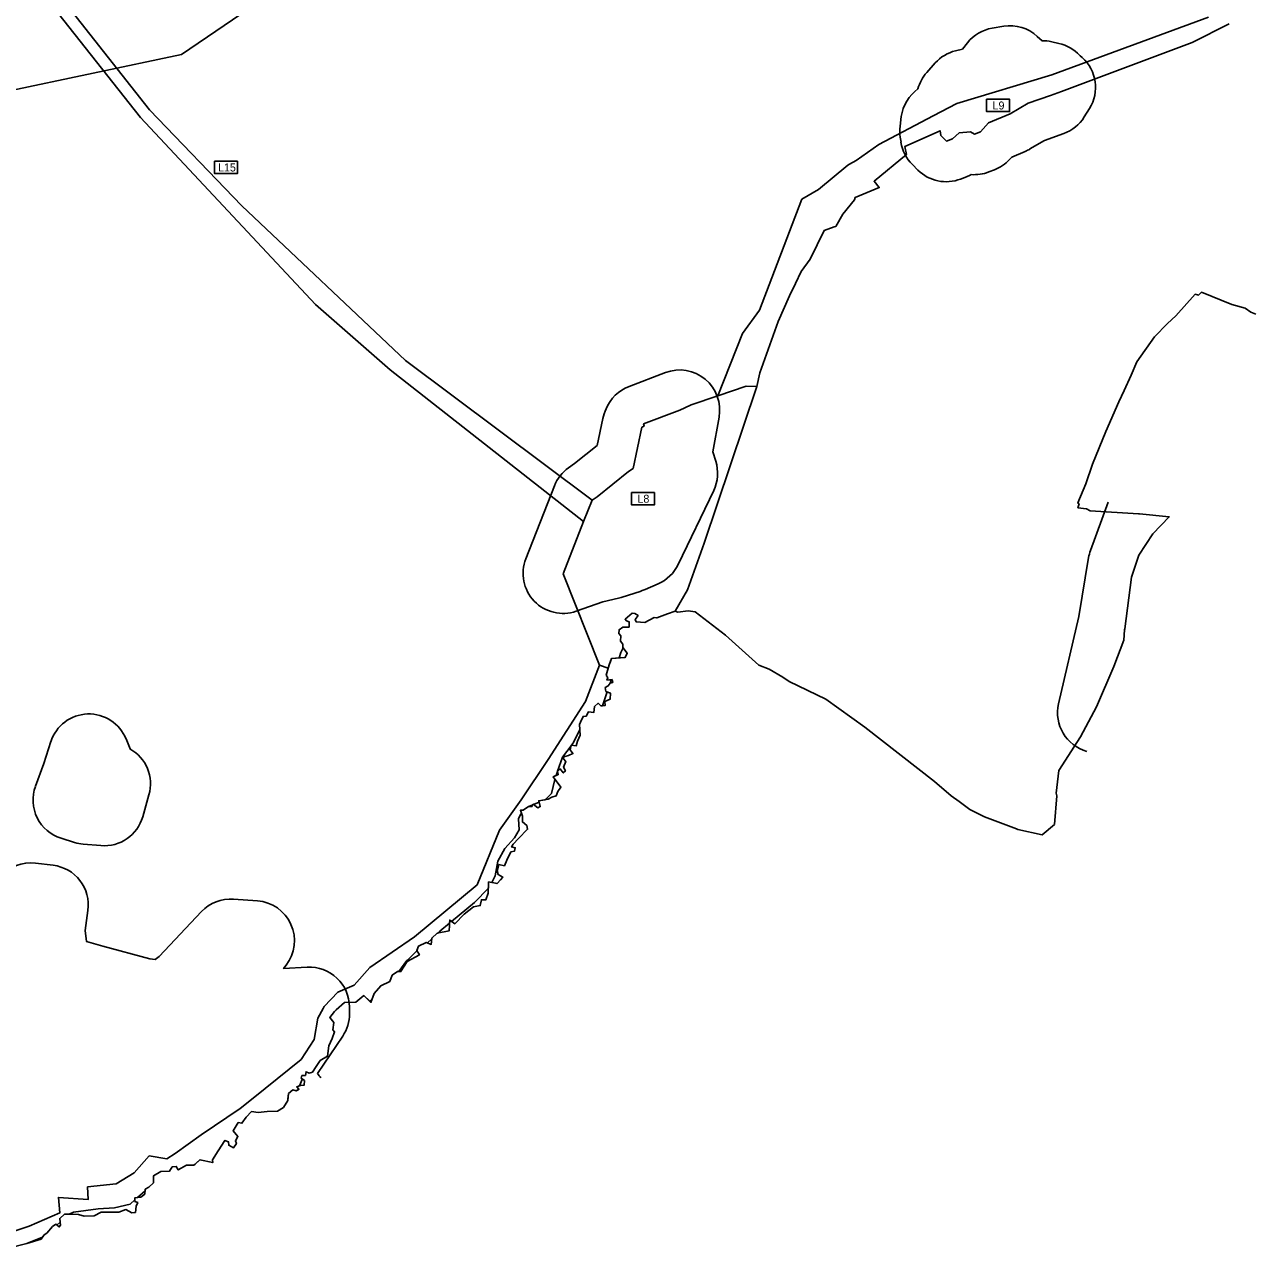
# Model space of a CAD drawing. Extents: x -547623 to -532764, y -1096714 to -1086523.
# Drawn here: x -541756 to -540221, y -1094468 to -1092939 of the extents above; entities that cross this region are included whole.
import ezdxf

# ---------------------------------------------------------------- set-up
doc = ezdxf.new("R2010")
doc.units = 0
for name, color, linetype in [('Vrstva 22', 7, 'Continuous'), ('Vrstva 23', 7, 'Continuous'), ('Vrstva 32', 7, 'Continuous'), ('Vrstva 33', 7, 'Continuous'), ('Vrstva 36', 7, 'Continuous')]:
    doc.layers.add(name, color=color, linetype=linetype)

msp = doc.modelspace()

# ---------------------------------------------------------------- linework, layer by layer
at = {"layer": 'Vrstva 22'}
for points in [[(-541614.2, -1092219.2), (-541528.1, -1092261.5), (-541473.1, -1092334.2), (-541450.6, -1092439.7), (-541395.2, -1092515.1), (-541374.9, -1092586.5), (-541384.1, -1092718), (-541463.6, -1092911.1), (-541559.8, -1092976.5), (-541891.2, -1093046.6)], [(-541777.7, -1094468.4), (-541753.1, -1094462.3), (-541733.3, -1094454.2), (-541731.4, -1094451.4), (-541727.8, -1094449.2), (-541721.1, -1094441), (-541716.9, -1094438.1), (-541715.3, -1094439.3), (-541711.2, -1094435.5), (-541711.8, -1094430.8), (-541705.7, -1094425.4), (-541700.1, -1094425.5), (-541694.7, -1094423.2), (-541663.7, -1094418.8), (-541643.5, -1094417.6), (-541623.8, -1094412.9), (-541617.9, -1094407.7), (-541618, -1094405.2), (-541614.6, -1094404.7), (-541605.1, -1094396.2), (-541604.9, -1094394.3), (-541600.6, -1094391.8), (-541594.8, -1094386.5), (-541594.6, -1094377.6), (-541585.5, -1094372.2), (-541574.6, -1094371.7), (-541571.3, -1094366.4), (-541566.3, -1094365.9), (-541563.8, -1094370.3), (-541553.4, -1094364.4), (-541544.1, -1094364.4), (-541536.7, -1094357.6), (-541520.7, -1094361), (-541520.9, -1094357.7), (-541513.9, -1094346.5), (-541505.5, -1094333.3), (-541500.8, -1094335.3), (-541500.6, -1094339.4), (-541494.5, -1094342.6), (-541491.1, -1094337.3), (-541492.4, -1094334.1), (-541489.1, -1094328.6), (-541495.2, -1094321.4), (-541488.7, -1094311.1), (-541484.1, -1094311.9), (-541479, -1094304.4), (-541472.3, -1094297.4), (-541463.9, -1094298.3), (-541452.7, -1094297.4), (-541439.8, -1094296.8), (-541432.3, -1094292.1), (-541426.7, -1094283.4), (-541425.9, -1094274.8), (-541420.7, -1094270), (-541416.5, -1094271.6), (-541413.9, -1094270), (-541413.5, -1094268.9), (-541415.6, -1094266.6), (-541412.1, -1094265.2), (-541409, -1094257.4), (-541409, -1094257.3), (-541408.5, -1094256.9), (-541410, -1094255.8), (-541409.1, -1094252.4), (-541404.9, -1094252.2), (-541404, -1094247.6), (-541400, -1094249.5), (-541396.1, -1094248), (-541391.4, -1094241.1), (-541386.2, -1094233.4), (-541377.4, -1094228.2), (-541375.6, -1094215), (-541371.4, -1094206), (-541368.4, -1094197.9), (-541370.5, -1094195.2), (-541369.3, -1094186.2), (-541374.2, -1094180), (-541368.6, -1094172.5), (-541356, -1094161.1), (-541341.8, -1094160.7), (-541331.8, -1094152.4), (-541324.5, -1094159.5), (-541321.7, -1094157.7), (-541318.8, -1094150), (-541310.6, -1094140.3), (-541299.5, -1094134.8), (-541296.5, -1094127), (-541289.9, -1094122.4), (-541288, -1094122.5), (-541277.9, -1094108.7), (-541277.4, -1094108.2), (-541276.4, -1094107.2), (-541265.5, -1094096.3), (-541265.7, -1094096), (-541263.3, -1094090.6), (-541253.9, -1094085.9), (-541252.4, -1094086.5), (-541246.9, -1094081.4), (-541246.9, -1094080.6), (-541240.1, -1094074.5), (-541239.5, -1094074.4), (-541237, -1094072), (-541224.7, -1094061.9), (-541224.5, -1094058), (-541222.1, -1094059.7), (-541193.6, -1094036.2), (-541176.2, -1094018.3), (-541175.9, -1094010.3), (-541171.9, -1094011.1), (-541167.8, -1094002.8), (-541164.2, -1093984.5), (-541155.6, -1093968.7), (-541143.4, -1093955.5), (-541137.7, -1093945.2), (-541138.6, -1093931.7), (-541135.7, -1093925.4), (-541134.9, -1093924.7), (-541136.2, -1093920.9), (-541132.7, -1093920.8), (-541126.1, -1093916), (-541125.2, -1093916.2), (-541124.9, -1093915.9), (-541120.6, -1093914.1), (-541120.1, -1093913.4), (-541119.7, -1093913.7), (-541112.8, -1093910.7), (-541113.2, -1093909), (-541105.6, -1093907.7), (-541104.6, -1093907.3), (-541097.1, -1093899.9), (-541093.1, -1093882.3), (-541093, -1093881.9), (-541095.1, -1093879), (-541091.4, -1093877.4), (-541089.7, -1093872.5), (-541089.8, -1093872.3), (-541089.6, -1093872.1), (-541083.6, -1093854.7), (-541072.9, -1093840.3), (-541072.8, -1093839.7), (-541072.5, -1093839.7), (-541069.8, -1093836), (-541061.8, -1093819.8), (-541062.1, -1093813.8), (-541061.2, -1093810.6), (-541057.9, -1093803.5), (-541053.8, -1093803.2), (-541051.2, -1093797.9), (-541044.4, -1093798.8), (-541043.5, -1093791.1), (-541039, -1093787.2), (-541035.6, -1093790.4), (-541033.7, -1093790.3), (-541027.7, -1093773), (-541029.3, -1093772.3), (-541030.1, -1093767.5), (-541026.3, -1093765.5), (-541024, -1093761.9), (-541023.8, -1093761.9), (-541022.4, -1093757.7), (-541028.1, -1093758.2), (-541027, -1093755.2), (-541028.8, -1093752.1), (-541025.3, -1093739.1), (-541022.3, -1093731.1), (-541012.9, -1093730.4), (-541010.5, -1093723.6), (-541007.9, -1093718), (-541008.3, -1093717.5), (-541008.1, -1093713.3), (-541011.2, -1093709.6), (-541010.5, -1093702.9), (-541013.3, -1093700), (-541012.8, -1093695.4), (-541008.3, -1093692.1), (-541000.3, -1093692), (-541000.1, -1093685.6), (-541003.7, -1093684.2), (-541005.3, -1093682.2), (-540996.3, -1093674.6), (-540993.1, -1093674.9), (-540989.1, -1093677.5), (-540992.6, -1093682.7), (-540991.5, -1093685.3), (-540980.8, -1093686.2), (-540969.1, -1093679.8), (-540965.7, -1093680.5), (-540952.4, -1093675.5), (-540942.7, -1093672.1), (-540939.3, -1093673.3), (-540926.5, -1093671.8), (-540917.9, -1093673.1), (-540879.9, -1093702.1), (-540838.1, -1093739.4), (-540825.3, -1093744.7), (-540808.3, -1093754.5), (-540800.3, -1093759.8), (-540754.6, -1093782.1), (-540705.7, -1093817.2), (-540618.6, -1093884.8), (-540597.9, -1093902.7), (-540587.9, -1093910), (-540574.7, -1093919.7), (-540556.2, -1093929.2), (-540516.1, -1093944.2), (-540514.3, -1093944.7), (-540484.3, -1093951.5), (-540468.6, -1093938.6), (-540465.8, -1093903), (-540466.7, -1093899.5), (-540463.3, -1093871), (-540436.1, -1093829.3), (-540416, -1093791.8), (-540394.4, -1093741.3), (-540382.1, -1093708.2), (-540381, -1093695.6), (-540380.8, -1093694.1), (-540372.3, -1093629.8), (-540363.4, -1093602), (-540345.9, -1093575.3), (-540325.2, -1093554.4), (-540362.4, -1093550.6), (-540363.9, -1093550.5), (-540424.3, -1093546.9), (-540428.5, -1093544.2), (-540439.5, -1093542.9), (-540437.9, -1093538), (-540439.7, -1093536.8), (-540429.5, -1093513), (-540421.3, -1093488.5), (-540404.4, -1093447.4), (-540388.2, -1093410.4), (-540381.6, -1093396.2), (-540372.8, -1093377), (-540365.7, -1093360.7), (-540343.8, -1093329.3), (-540327.3, -1093312.6), (-540317.1, -1093303.2), (-540293, -1093276.1), (-540288.8, -1093277.2), (-540284.8, -1093273.6), (-540246.9, -1093288.8), (-540230.3, -1093293.4), (-540223.3, -1093298.3), (-540217.1, -1093300.8)]]:
    msp.add_lwpolyline(points, dxfattribs=at)
at = {"layer": 'Vrstva 23'}
for p, q in [((-540532.2, -1092941.3), (-540546.4, -1092943.6)), ((-540484.3, -1092959.3), (-540490.2, -1092953.9)), ((-540463.2, -1092962.6), (-540472.1, -1092960.6)), ((-540617.7, -1092987.1), (-540628.3, -1092999)), ((-540434.2, -1092980.3), (-540436.8, -1092978.1)), ((-540431.5, -1093054.6), (-540425, -1093044)), ((-540660.2, -1093054.2), (-540661.7, -1093066.2)), ((-540661.5, -1093079.9), (-540660.5, -1093086.2)), ((-540522.2, -1093104.7), (-540505.4, -1093097.6)), ((-540646.3, -1093114.1), (-540639.4, -1093121)), ((-540524.9, -1093107.6), (-540522.2, -1093104.7)), ((-540586.1, -1093132.1), (-540578.5, -1093129.2)), ((-540550.9, -1093123.3), (-540543.8, -1093120.6)), ((-540954.9, -1093374), (-541000.3, -1093391.3)), ((-541093.6, -1093515.4), (-541129.4, -1093606.6)), ((-540938.8, -1093613.7), (-540894.6, -1093521.4)), ((-540401.8, -1093536), (-540423.7, -1093596.3)), ((-541010.3, -1093654.8), (-540985.2, -1093646.9)), ((-540980.4, -1093645.1), (-540964, -1093638)), ((-541624, -1093844.1), (-541629, -1093831.8)), ((-541608.1, -1093928.9), (-541600.3, -1093901.5)), ((-541710.1, -1093955.8), (-541693.3, -1093961)), ((-541682.6, -1093963.1), (-541660.4, -1093965)), ((-541720.1, -1093989.6), (-541742, -1093986.9)), ((-541464.9, -1094034), (-541494.6, -1094031.8)), ((-541349.7, -1094175), (-541349.7, -1094166.7)), ((-541389.7, -1094249.9), (-541358.2, -1094203))]:
    msp.add_line(p, q, dxfattribs=at)
for points in [[(-540577.5, -1092961.9), (-540583.8, -1092969.7), (-540592.6, -1092971.9)], [(-540499.4, -1093094.6), (-540481, -1093083.9), (-540457.2, -1093075.3)], [(-541033.1, -1093431.4), (-541040.4, -1093464.9), (-541068.6, -1093487.7), (-541076.1, -1093493)], [(-540892.1, -1093484.6), (-540895.8, -1093472.8), (-540887.9, -1093429.8)], [(-540426, -1093605.2), (-540438.3, -1093678.8), (-540463.6, -1093787.7)], [(-541066.4, -1093672.1), (-541033.2, -1093660.5), (-541013.6, -1093655.8)], [(-541723, -1093835.1), (-541731.8, -1093862.5), (-541742.2, -1093890.9)], [(-541534.8, -1094047.5), (-541587.5, -1094103.6), (-541592.7, -1094107.2), (-541599.2, -1094106.5), (-541657.8, -1094090.8), (-541678.2, -1094084.9), (-541680.1, -1094071.1), (-541676.7, -1094045.9)], [(-541402.5, -1094116.9), (-541432.2, -1094118.6), (-541428.9, -1094114.4)]]:
    msp.add_lwpolyline(points, dxfattribs=at)
for centre, start, end in [((-540538.4, -1092993), 99.2534, 141.5424), ((-540524.1, -1092990.6), 47.236, 99.2534), ((-540483.2, -1093009.3), 77.2619, 91.3423), ((-540580.4, -1093020.4), 104.0736, 138.232), ((-540474.2, -1093011.4), 42.6327, 77.2619), ((-540470, -1093015.4), 48.3246, 49.3142), ((-540467.4, -1093017.7), 328.1995, 48.3246), ((-540591, -1093032.3), 138.232, 165.1966), ((-540610.5, -1093060.4), 125.1843, 172.8573), ((-540612, -1093072.4), 172.8573, 188.6976), ((-540474, -1093028.2), 289.6731, 328.1995), ((-540611.1, -1093078.6), 188.6976, 225.2065), ((-540524.7, -1093051.5), 292.7173, 300.3391), ((-540561.9, -1093074), 291.2311, 317.7161), ((-540604.1, -1093085.5), 225.2065, 291.1954), ((-540596.6, -1093082.6), 291.1954, 298.3481), ((-540569, -1093076.7), 265.6199, 291.2311), ((-540937.1, -1093420.7), 349.5868, 110.8529), ((-540982.5, -1093438), 110.8529, 158.1729), ((-540984.3, -1093442.1), 153.0889, 167.6897), ((-541047, -1093533.7), 125.5439, 158.5593), ((-540939.7, -1093499.8), 334.4288, 17.6481), ((-540376.7, -1093613.4), 160.0468, 170.5482), ((-541082.8, -1093624.9), 158.5593, 289.2173), ((-540983.9, -1093592.1), 293.4551, 334.4288), ((-541000.3, -1093599.2), 287.5813, 293.4551), ((-541025.4, -1093607.2), 283.6374, 287.5813), ((-540414.9, -1093799), 166.8917, 254.7011), ((-541675.4, -1093850.5), 21.9392, 162.1266), ((-541648.4, -1093887.8), 344.0823, 60.8667), ((-541695.2, -1093908.1), 159.9636, 252.6693), ((-541656.2, -1093915.2), 265.198, 344.0823), ((-541678.4, -1093913.3), 252.6693, 265.198), ((-541748.1, -1094036.5), 82.9716, 139.1347), ((-541726.2, -1094039.2), 352.3407, 82.9716), ((-541498.3, -1094081.7), 85.7735, 136.8074), ((-541468.5, -1094083.9), 322.4508, 85.7735), ((-541399.7, -1094166.9), 0.2071, 93.2322), ((-541399.7, -1094175.2), 326.0973, 0.2071), ((-541426.8, -1094283.5), 34.3894, 42.1374)]:
    msp.add_arc(centre, 50, start, end, dxfattribs=at)
at = {"layer": 'Vrstva 32'}
for points in [[(-541037.5, -1093739.4), (-541026.4, -1093743.1), (-541025.3, -1093739.1), (-541023.7, -1093734.8), (-541022.3, -1093731.1), (-541005.1, -1093729.9), (-541002.6, -1093724.6), (-541008.3, -1093717.5), (-541008.1, -1093713.3), (-541011.2, -1093709.6), (-541010.5, -1093702.9), (-541013.3, -1093700), (-541012.8, -1093695.4), (-541008.3, -1093692.1), (-541000.3, -1093692), (-541000.1, -1093685.6), (-541003.7, -1093684.2), (-541005.3, -1093682.2), (-540996.3, -1093674.6), (-540993.1, -1093674.9), (-540989.1, -1093677.5), (-540992.6, -1093682.7), (-540991.5, -1093685.3), (-540980.8, -1093686.2), (-540969.1, -1093679.8), (-540965.7, -1093680.5), (-540952.4, -1093675.5), (-540942.7, -1093672.1), (-540927.5, -1093645.4), (-540906.7, -1093587), (-540840.5, -1093391.2), (-540854, -1093391), (-540889.3, -1093403), (-540922.6, -1093414.2), (-540930.7, -1093417.9), (-540936.9, -1093421.1), (-540982.2, -1093437.9), (-540981.5, -1093440.8), (-540984.2, -1093442.2), (-540995.3, -1093493.8), (-541000.9, -1093497.5), (-541040.2, -1093529.3), (-541046.4, -1093533.4), (-541057.1, -1093560.2), (-541082.9, -1093625.4)], [(-541082.9, -1093625.4), (-541037.5, -1093739.4)]]:
    msp.add_lwpolyline(points, dxfattribs=at)
at = {"layer": 'Vrstva 33'}
for points in [[(-541763.4, -1092788.4), (-541753.9, -1092814), (-541739.8, -1092850.1), (-541708.5, -1092907.4), (-541599.8, -1093045.5), (-541484.2, -1093165.6), (-541279.8, -1093359), (-541046.4, -1093533.4), (-541057.1, -1093560.2), (-541298.9, -1093370.5), (-541392.1, -1093289), (-541611.1, -1093055.4), (-541720.8, -1092916), (-541721.5, -1092914.9), (-541753.6, -1092856.2), (-541769.6, -1092820.4)], [(-540250.4, -1092938.3), (-540296.7, -1092961.6), (-540459.9, -1093022.6), (-540473.7, -1093027.6), (-540501.7, -1093037.5), (-540524.2, -1093050.7), (-540551.2, -1093062.1), (-540561.3, -1093073.2), (-540568.8, -1093076.1), (-540573.6, -1093073.2), (-540587.8, -1093074.6), (-540596.3, -1093081.9), (-540603.8, -1093084.7), (-540610.6, -1093077.8), (-540611.7, -1093071.8), (-540655.6, -1093091.3), (-540653.7, -1093101.6), (-540694.2, -1093134.8), (-540687.7, -1093142.8), (-540717.6, -1093155), (-540718.5, -1093158.3), (-540733, -1093175.9), (-540742, -1093191.4), (-540744.1, -1093191.9), (-540756.7, -1093196.5), (-540774, -1093232.2), (-540785.2, -1093247.7), (-540792.5, -1093262.6), (-540800, -1093278), (-540814.2, -1093310), (-540837, -1093374.3), (-540840.5, -1093391.2), (-540854, -1093391), (-540889.3, -1093403), (-540858.7, -1093325.2), (-540837.2, -1093296.1), (-540784.5, -1093157.4), (-540763.5, -1093145.2), (-540726.9, -1093114.6), (-540724.8, -1093113.4), (-540716.7, -1093109), (-540688.1, -1093088.9), (-540620.5, -1093053.3), (-540590.9, -1093037.7), (-540471.9, -1093001.8), (-540276.3, -1092929.7)], [(-541382.7, -1094168.4), (-541381.4, -1094166.2), (-541364.4, -1094148.2), (-541343.7, -1094139.4), (-541324.5, -1094117.3), (-541268.3, -1094078.9), (-541190, -1094014), (-541162.1, -1093945.6), (-541135.4, -1093907.8), (-541101.4, -1093857.6), (-541054.8, -1093785.1), (-541037.5, -1093739.4), (-541026.4, -1093743.1), (-541028.8, -1093752.1), (-541027, -1093755.2), (-541028.1, -1093758.2), (-541021.5, -1093757.6), (-541020.8, -1093761.1), (-541024, -1093761.9), (-541026.3, -1093765.5), (-541030.1, -1093767.5), (-541029.3, -1093772.3), (-541023.4, -1093774.7), (-541023.8, -1093782), (-541030.6, -1093784.9), (-541030.3, -1093790), (-541035.6, -1093790.4), (-541039, -1093787.2), (-541043.5, -1093791.1), (-541044.4, -1093798.8), (-541051.2, -1093797.9), (-541053.8, -1093803.2), (-541057.9, -1093803.5), (-541061.2, -1093810.6), (-541062.1, -1093813.8), (-541061.3, -1093827.1), (-541064.8, -1093834.5), (-541066.4, -1093840.3), (-541072.8, -1093839.7), (-541074.1, -1093845.5), (-541070.5, -1093850), (-541076.1, -1093852.4), (-541081.9, -1093853.9), (-541082.1, -1093856.7), (-541079.5, -1093860), (-541082.1, -1093867), (-541079.8, -1093871.6), (-541082.5, -1093874.1), (-541086.3, -1093869.2), (-541089.8, -1093872.3), (-541088.8, -1093876.2), (-541095.1, -1093879), (-541085.6, -1093892.1), (-541089.5, -1093897.6), (-541091.3, -1093902.8), (-541096.9, -1093904.4), (-541101.6, -1093907), (-541113.2, -1093909), (-541111.4, -1093916.3), (-541114.2, -1093917.7), (-541120.1, -1093913.4), (-541122.4, -1093916.6), (-541126.1, -1093916), (-541132.7, -1093920.8), (-541136.2, -1093920.9), (-541135.8, -1093921.9), (-541133.7, -1093928.4), (-541133.6, -1093935.4), (-541128.2, -1093939.8), (-541127.1, -1093944.5), (-541138.5, -1093956.2), (-541145, -1093963.1), (-541147.1, -1093966.6), (-541142.6, -1093967.7), (-541143.4, -1093971.9), (-541148.1, -1093972.9), (-541153.1, -1093983), (-541156.2, -1093990.1), (-541163.1, -1093988.8), (-541165, -1093996.4), (-541163.8, -1094001.3), (-541158.3, -1094004.3), (-541161.1, -1094007.6), (-541165.3, -1094012.5), (-541175.9, -1094010.3), (-541176.3, -1094024.6), (-541179.3, -1094032.7), (-541184.9, -1094032.7), (-541186.4, -1094039.9), (-541194.7, -1094041.4), (-541206.6, -1094050.8), (-541218, -1094062.7), (-541224.5, -1094058), (-541225.3, -1094071.7), (-541240.1, -1094074.5), (-541246.9, -1094080.6), (-541247.5, -1094088.5), (-541253.9, -1094085.9), (-541263.3, -1094090.6), (-541265.7, -1094096), (-541262.4, -1094101.4), (-541277.5, -1094109.7), (-541286.2, -1094122.6), (-541289.9, -1094122.4), (-541296.5, -1094127), (-541299.5, -1094134.8), (-541310.6, -1094140.3), (-541318.8, -1094150), (-541323, -1094161), (-541331.8, -1094152.4), (-541341.8, -1094160.7), (-541356, -1094161.1), (-541366.2, -1094170.3)], [(-541779, -1094449.9), (-541750, -1094440.5), (-541711.8, -1094423.9), (-541713.5, -1094404.7), (-541676.5, -1094407.3), (-541677, -1094391.4), (-541641.2, -1094387.8), (-541618.8, -1094374), (-541600.1, -1094352.8), (-541578, -1094356.4), (-541567.6, -1094349.9), (-541535.2, -1094326.4), (-541486.2, -1094293.5), (-541470, -1094280.7), (-541410.2, -1094232.3), (-541393.9, -1094207.4), (-541389.5, -1094180.7), (-541382.7, -1094168.4)], [(-541366.2, -1094170.3), (-541368.6, -1094172.5), (-541374.2, -1094180), (-541369.3, -1094186.2), (-541370.5, -1094195.2), (-541368.4, -1094197.9), (-541371.4, -1094206), (-541375.6, -1094215), (-541377.4, -1094228.2), (-541386.2, -1094233.4), (-541391.4, -1094241.1), (-541396.1, -1094248), (-541400, -1094249.5), (-541404, -1094247.6), (-541404.9, -1094252.2), (-541409.1, -1094252.4), (-541410, -1094255.8), (-541406, -1094258.7), (-541406.5, -1094264.5), (-541411, -1094264.8), (-541415.6, -1094266.6), (-541413, -1094269.5), (-541416.5, -1094271.6), (-541420.7, -1094270), (-541425.9, -1094274.8), (-541426.6, -1094281.8), (-541426.7, -1094283.4), (-541432.3, -1094292.1), (-541439.8, -1094296.8), (-541452.7, -1094297.4), (-541463.9, -1094298.3), (-541472.3, -1094297.4), (-541479, -1094304.4), (-541484.1, -1094311.9), (-541488.7, -1094311.1), (-541495.2, -1094321.4), (-541489.1, -1094328.6), (-541492.4, -1094334.1), (-541491.1, -1094337.3), (-541494.5, -1094342.6), (-541500.6, -1094339.4), (-541500.8, -1094335.3), (-541505.5, -1094333.3), (-541513.9, -1094346.5), (-541520.9, -1094357.7), (-541520.7, -1094361), (-541536.7, -1094357.6), (-541542.6, -1094363), (-541544.1, -1094364.4), (-541553.4, -1094364.4), (-541563.8, -1094370.3), (-541566.3, -1094365.9), (-541571.3, -1094366.4), (-541574.6, -1094371.7), (-541585.5, -1094372.2), (-541594.6, -1094377.6), (-541594.8, -1094386.5), (-541600.6, -1094391.8), (-541604.9, -1094394.3), (-541605.6, -1094400.4), (-541610.7, -1094404.1), (-541618, -1094405.2), (-541617.9, -1094409.7), (-541614.4, -1094411), (-541616.3, -1094415.5), (-541617.3, -1094423.3), (-541621.7, -1094423.9), (-541629.4, -1094419.7), (-541637.8, -1094423.2), (-541659.9, -1094423.1), (-541668.7, -1094427.7), (-541681.3, -1094427.9), (-541688.5, -1094425.9), (-541705.7, -1094425.4), (-541711.8, -1094430.8), (-541710.7, -1094439.3), (-541712.4, -1094441.4), (-541716.9, -1094438.1), (-541721.1, -1094441), (-541727.8, -1094449.2), (-541731.4, -1094451.4), (-541735.1, -1094456.9), (-541752.8, -1094462.2), (-541777.7, -1094468.4)]]:
    msp.add_lwpolyline(points, dxfattribs=at)
at = {"layer": 'Vrstva 36'}
for points in [[(-540553.6, -1093032.4), (-540524.9, -1093032.4), (-540524.9, -1093047.9), (-540553.6, -1093047.9)], [(-541518.4, -1093109.9), (-541489.8, -1093109.9), (-541489.8, -1093125.4), (-541518.4, -1093125.4)], [(-540997.3, -1093523.9), (-540968.7, -1093523.9), (-540968.7, -1093539.4), (-540997.3, -1093539.4)]]:
    msp.add_lwpolyline(points, close=True, dxfattribs=at)

# ---------------------------------------------------------------- texts
for s, p in [('L9', (-540546.1, -1093045.2)), ('L15', (-541514.1, -1093122.7)), ('L8', (-540989.9, -1093536.6))]:
    msp.add_text(s, height=10, dxfattribs=at).set_placement(p)

doc.saveas('drawing.dxf')
